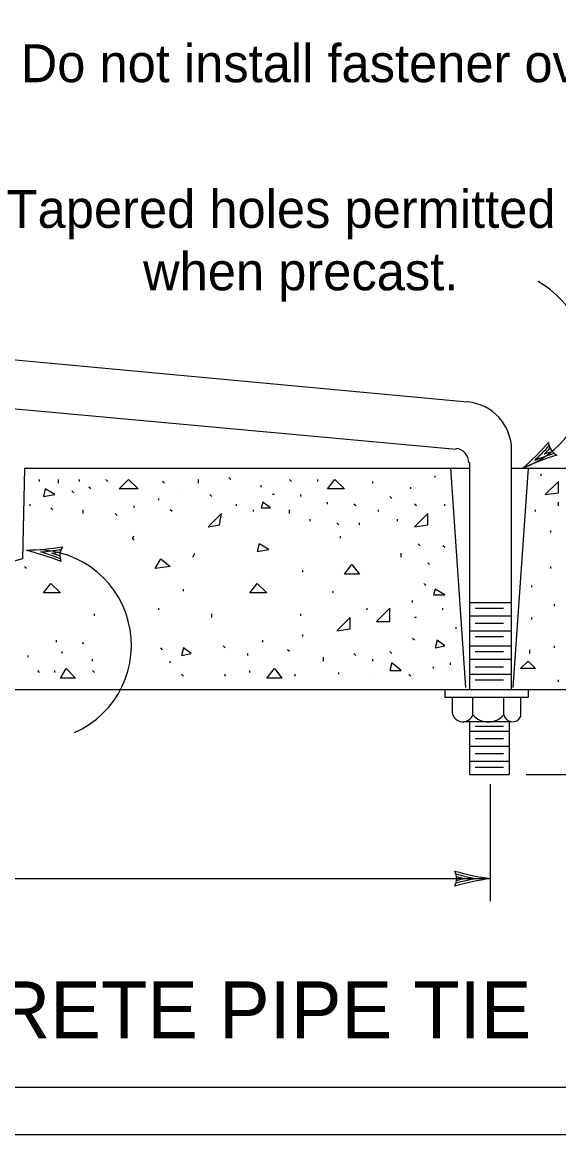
# Model space of a CAD drawing. Extents: x 0 to 390, y 0 to 265.
# Drawn here: x 177.2 to 205.5, y 0 to 58.8 of the extents above; entities that cross this region are included whole.
import ezdxf

# ---------------------------------------------------------------- set-up
doc = ezdxf.new("R2010")
doc.units = 0
doc.layers.add('D_Details', color=7, linetype='Continuous')
doc.layers.add('Default', color=7, linetype='Continuous')

msp = doc.modelspace()

# ---------------------------------------------------------------- linework, layer by layer
at = {"layer": 'D_Details'}
for p, q in [((162.067, 42.341), (200.667, 38.741)), ((164.067, 39.541), (200.067, 36.241)), ((202.967, 36.241), (202.967, 23.541)), ((200.767, 35.541), (200.767, 23.541)), ((177.267, 35.241), (200.767, 35.241)), ((188.167, 34.641), (188.067, 34.741)), ((198.967, 34.741), (198.967, 34.841)), ((199.767, 35.241), (200.567, 23.641)), ((202.967, 35.241), (212.067, 35.241)), ((203.867, 35.241), (203.067, 23.641)), ((204.567, 34.841), (204.567, 34.941)), ((178.067, 34.541), (178.067, 34.641)), ((179.067, 34.441), (179.067, 34.641)), ((180.167, 34.541), (180.167, 34.641)), ((180.767, 34.141), (180.667, 34.241)), ((181.667, 34.541), (181.567, 34.641)), ((184.667, 34.441), (184.567, 34.541)), ((186.467, 34.441), (186.467, 34.641)), ((189.767, 34.241), (189.767, 34.341)), ((191.367, 34.541), (191.267, 34.641)), ((192.767, 34.541), (192.767, 34.641)), ((195.667, 34.441), (195.667, 34.541)), ((197.667, 34.141), (197.667, 34.241)), ((179.867, 33.941), (179.767, 34.041)), ((184.367, 33.541), (184.367, 33.641)), ((185.667, 33.841), (185.667, 33.841)), ((187.167, 33.741), (187.067, 33.841)), ((190.467, 33.841), (190.367, 33.841)), ((191.867, 33.741), (191.867, 33.841)), ((196.667, 33.641), (196.567, 33.741)), ((177.567, 33.241), (177.567, 33.341)), ((178.767, 33.041), (178.667, 33.141)), ((180.367, 32.841), (180.367, 33.041)), ((183.067, 33.141), (183.067, 33.241)), ((185.067, 32.941), (184.967, 33.041)), ((188.467, 33.241), (188.467, 33.341)), ((189.367, 32.941), (189.367, 33.041)), ((191.267, 32.841), (191.267, 33.041)), ((193.267, 33.341), (193.267, 33.441)), ((194.767, 33.241), (194.667, 33.341)), ((195.967, 32.941), (195.967, 33.041)), ((197.967, 33.241), (197.867, 33.341)), ((199.467, 33.241), (199.467, 33.341)), ((204.267, 32.941), (204.267, 33.041)), ((205.467, 33.241), (205.467, 33.441)), ((182.167, 32.741), (182.067, 32.841)), ((192.367, 32.441), (192.367, 32.541)), ((196.967, 32.441), (196.967, 32.541)), ((193.867, 32.241), (193.767, 32.341)), ((194.967, 32.241), (194.967, 32.341)), ((205.067, 31.841), (205.067, 31.941)), ((182.967, 31.541), (183.067, 31.641)), ((183.067, 31.441), (182.967, 31.541)), ((193.967, 31.541), (193.967, 31.641)), ((198.167, 31.141), (198.067, 31.241)), ((186.167, 30.541), (186.267, 30.741)), ((197.167, 30.541), (197.167, 30.741)), ((199.467, 31.041), (199.367, 31.141)), ((177.367, 29.941), (177.267, 30.041)), ((198.667, 30.141), (198.567, 30.241)), ((205.067, 29.941), (205.067, 30.041)), ((191.967, 29.741), (191.967, 29.841)), ((185.667, 28.741), (185.667, 28.841)), ((198.467, 29.041), (198.367, 29.141)), ((204.067, 28.941), (204.067, 29.041)), ((193.567, 28.641), (193.567, 28.741)), ((197.767, 28.141), (197.767, 28.241)), ((184.367, 27.741), (184.367, 27.841)), ((195.367, 27.741), (195.367, 27.841)), ((199.367, 27.741), (199.367, 27.841)), ((200.767, 28.141), (202.967, 28.141)), ((201.067, 27.841), (202.567, 27.841)), ((205.267, 27.941), (205.267, 28.041)), ((180.967, 27.441), (180.967, 27.541)), ((187.167, 27.341), (187.167, 27.541)), ((191.867, 27.441), (191.867, 27.541)), ((197.967, 27.341), (197.867, 27.341)), ((200.767, 27.441), (202.967, 27.441)), ((204.067, 27.241), (204.067, 27.341)), ((200.067, 26.741), (200.067, 26.841)), ((200.767, 26.641), (202.967, 26.641)), ((201.067, 27.041), (202.567, 27.041)), ((178.967, 26.041), (178.967, 26.141)), ((180.367, 25.941), (180.367, 26.041)), ((189.867, 26.041), (189.867, 26.141)), ((191.967, 26.341), (191.967, 26.441)), ((197.867, 26.141), (197.767, 26.241)), ((201.067, 26.341), (202.567, 26.341)), ((177.467, 25.241), (177.467, 25.341)), ((179.267, 25.441), (179.267, 25.541)), ((184.567, 25.641), (184.467, 25.741)), ((187.867, 25.741), (187.767, 25.841)), ((189.067, 25.341), (189.067, 25.441)), ((191.267, 25.541), (191.167, 25.641)), ((194.767, 25.341), (194.667, 25.441)), ((196.667, 25.441), (196.567, 25.541)), ((200.767, 25.841), (202.967, 25.841)), ((201.067, 25.541), (202.567, 25.541)), ((203.967, 25.441), (203.967, 25.641)), ((205.267, 25.741), (205.267, 25.841)), ((180.867, 25.041), (180.867, 25.141)), ((184.967, 24.941), (184.967, 25.041)), ((193.067, 25.041), (193.067, 25.241)), ((195.667, 25.041), (195.667, 25.141)), ((198.867, 24.641), (198.867, 24.741)), ((199.767, 24.841), (199.767, 24.941)), ((200.767, 25.141), (202.967, 25.141)), ((201.067, 24.741), (202.567, 24.741)), ((178.067, 24.441), (177.967, 24.541)), ((178.867, 24.441), (178.867, 24.541)), ((180.967, 24.441), (180.867, 24.541)), ((185.667, 24.241), (185.567, 24.341)), ((187.867, 24.241), (187.867, 24.341)), ((189.167, 24.441), (189.167, 24.541)), ((191.567, 24.241), (191.567, 24.341)), ((193.867, 24.341), (193.867, 24.441)), ((195.667, 24.441), (195.667, 24.441)), ((197.667, 24.241), (197.567, 24.341)), ((200.767, 24.341), (202.967, 24.341)), ((165.967, 23.541), (212.067, 23.541)), ((199.467, 23.541), (203.867, 23.541)), ((199.467, 23.541), (199.467, 23.141)), ((200.767, 23.841), (200.767, 23.541)), ((200.767, 23.541), (202.867, 23.541)), ((201.067, 24.041), (202.567, 24.041)), ((203.867, 23.541), (203.867, 23.141)), ((205.467, 23.941), (205.467, 24.041)), ((199.467, 23.141), (203.867, 23.141)), ((199.867, 23.141), (199.867, 22.282)), ((200.949, 22.192), (200.949, 23.141)), ((202.591, 22.192), (202.591, 23.141)), ((203.467, 23.141), (203.467, 22.09)), ((200.467, 21.841), (202.967, 21.841)), ((200.767, 21.841), (200.767, 19.041)), ((202.867, 21.841), (202.867, 19.041)), ((200.767, 21.341), (202.867, 21.341)), ((201.067, 21.604), (202.567, 21.604)), ((201.067, 20.941), (202.567, 20.941)), ((200.767, 20.541), (202.867, 20.541)), ((201.067, 20.157), (202.567, 20.157)), ((200.767, 19.741), (202.867, 19.741)), ((201.067, 19.441), (202.567, 19.441)), ((200.767, 19.041), (202.867, 19.041)), ((203.767, 19.041), (217.567, 19.041)), ((201.867, 18.541), (201.867, 12.341)), ((140.967, 13.541), (201.867, 13.541))]:
    msp.add_line(p, q, dxfattribs=at)
msp.add_lwpolyline([(177.267, 35.241), (177.167, 30.441), (166.267, 27.341), (165.967, 23.541)], dxfattribs=at)
for points in [[(178.267, 33.741), (178.867, 33.841), (178.367, 34.141)], [(182.267, 34.141), (182.767, 34.641), (183.267, 34.141)], [(193.267, 34.141), (193.667, 34.641), (194.167, 34.141)], [(205.467, 33.941), (205.467, 34.541), (204.767, 33.841)], [(189.767, 33.141), (190.267, 33.141), (189.867, 33.441)], [(187.567, 32.241), (187.667, 32.841), (186.967, 32.141)], [(198.567, 32.241), (198.567, 32.841), (197.867, 32.141)], [(189.567, 30.841), (190.167, 30.941), (189.667, 31.241)], [(184.167, 29.941), (184.467, 30.441), (184.967, 30.041)], [(194.167, 29.641), (194.567, 30.141), (194.967, 29.641)], [(178.267, 28.641), (178.667, 29.141), (179.167, 28.641)], [(189.167, 28.641), (189.567, 29.141), (190.067, 28.641)], [(198.867, 28.541), (199.467, 28.541), (198.967, 28.841)], [(196.567, 27.141), (196.567, 27.841), (195.867, 27.141)], [(194.467, 26.741), (194.467, 27.341), (193.767, 26.641)], [(198.967, 25.741), (199.467, 25.841), (199.067, 26.141)], [(185.567, 25.341), (186.067, 25.441), (185.667, 25.741)], [(196.567, 24.541), (197.167, 24.541), (196.667, 24.941)], [(203.467, 24.641), (203.867, 25.041), (204.267, 24.641)], [(179.167, 24.141), (179.467, 24.641), (179.967, 24.141)], [(190.067, 24.141), (190.467, 24.641), (190.867, 24.141)]]:
    msp.add_lwpolyline(points, close=True, dxfattribs=at)
for centre, radius, start, end in [((201.674, 40.359), 5.466, 290.53351, 60.1126), ((200.456, 36.209), 2.54, 0, 84.67156), ((194.381, 45.867), 14.063, 310.91615, 318.72784), ((205.82, 36.683), 0.874, 186.13116, 239.70115), ((199.978, 35.524), 0.762, 0, 84.7761), ((209.516, 22.487), 14.063, 107.10268, 114.91615), ((209.516, 22.487), 14.188, 107.48608, 111.91516), ((194.381, 45.867), 14.188, 313.91715, 318.34623), ((194.381, 45.867), 14.313, 316.27552, 318.08708), ((209.516, 22.487), 14.313, 107.74523, 109.55679), ((176.881, 44.945), 14.063, 271.99821, 279.8099), ((177.874, 25.873), 5.044, 293.75285, 95.72089), ((173.969, 17.247), 14.063, 68.18474, 75.99821), ((176.881, 44.945), 14.188, 274.99921, 279.42829), ((173.969, 17.247), 14.188, 68.56814, 72.99722), ((176.881, 44.945), 14.313, 277.35758, 279.16914), ((173.969, 17.247), 14.313, 68.82729, 70.63885), ((180.012, 30.614), 0.874, 147.21322, 200.78321), ((200.421, 22.393), 0.565, 191.36945, 339.15338), ((201.769, 22.935), 1.107, 222.15724, 317.84277), ((203.048, 22.306), 0.472, 193.95799, 332.68832), ((203.824, 27.467), 14.063, 254.18653, 262), ((199.212, 13.541), 0.874, 333.215, 26.78499), ((203.824, -0.385), 14.063, 98, 105.81169), ((203.824, 27.467), 14.188, 254.56992, 258.99901), ((203.824, -0.385), 14.188, 101.00099, 105.43008), ((203.824, 27.467), 14.313, 254.82908, 256.64064), ((203.824, -0.385), 14.313, 103.35937, 105.17092)]:
    msp.add_arc(centre, radius, start, end, dxfattribs=at)
at = {"layer": 'Default'}
for points in [[(0, 265), (326.25, 265), (326.25, 255), (390, 255), (390, 37.5), (315, 37.5), (315, 0), (0, 0)], [(0, 262.5), (326.25, 262.5), (326.25, 252.5), (390, 252.5), (390, 40), (315, 40), (315, 2.5), (0, 2.5)]]:
    msp.add_lwpolyline(points, close=True, dxfattribs=at)

# ---------------------------------------------------------------- texts
at = {"layer": 'D_Details'}
for s, height, p in [('Do not install fastener over pipe joint.', 2, (177.068, 55.643)), ('Tapered holes permitted', 2, (176.329, 47.943)), ('when precast.', 2, (183.533, 44.643)), ('SUPPLEMENTAL CONCRETE PIPE TIE', 3, (130.702, 5.105))]:
    msp.add_text(s, height=height, dxfattribs=at).set_placement(p)

doc.saveas('drawing.dxf')
